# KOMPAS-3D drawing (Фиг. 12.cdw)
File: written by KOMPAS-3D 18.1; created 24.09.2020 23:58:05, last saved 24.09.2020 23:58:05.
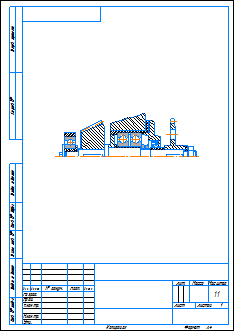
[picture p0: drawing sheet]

Sheet 1: A4, portrait

Document properties: Автор: user; Полное имя файла: C:\Users\user\Desktop\Задания\Фиг. 12.cdw

Title block, sheet 1: scale: 1:1; Количество листов документа: 1; Форматы листов документа: A4

Dimensions and other numbers on the sheet: 1:1; 1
